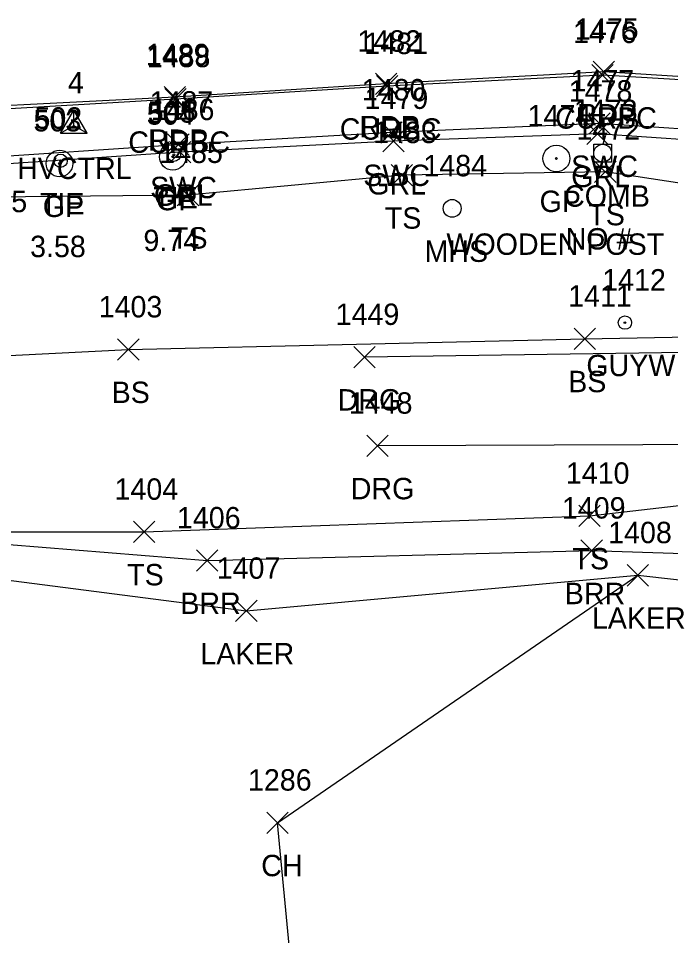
# Model space of a CAD drawing. Extents: x 1716490 to 1717645, y 888034 to 890004.
# Drawn here: x 1717454.4 to 1717515.4, y 888173.5 to 888259.2 of the extents above; entities that cross this region are included whole.
import ezdxf

# ---------------------------------------------------------------- set-up
doc = ezdxf.new("R2010")
doc.units = 0
for name, color, linetype in [('C_A', 7, 'Continuous'), ('C_C', 7, 'Continuous'), ('C_I', 7, 'Continuous'), ('CBP', 7, 'Continuous'), ('CPSM', 7, 'Continuous'), ('L_A', 7, 'Continuous'), ('L_I', 7, 'Continuous'), ('L_TIC', 7, 'Continuous'), ('LABL', 7, 'Continuous'), ('LAWE', 7, 'Continuous'), ('LELB', 7, 'Continuous'), ('LSOGP', 7, 'Continuous'), ('P_A', 7, 'Continuous'), ('P_I', 7, 'Continuous'), ('P_TIC', 7, 'Continuous'), ('PET', 7, 'Continuous'), ('R_A', 7, 'Continuous'), ('R_C', 7, 'Continuous'), ('R_I', 7, 'Continuous'), ('R_TIC', 7, 'Continuous'), ('RC', 7, 'Continuous'), ('RDG', 7, 'Continuous'), ('RGP', 7, 'Continuous'), ('RGR', 7, 'Continuous'), ('RSW', 7, 'Continuous'), ('U_A', 7, 'Continuous'), ('U_C', 7, 'Continuous'), ('U_I', 7, 'Continuous'), ('UP', 7, 'Continuous'), ('UPGW', 7, 'Continuous'), ('USMH', 7, 'Continuous')]:
    doc.layers.add(name, color=color, linetype=linetype)

msp = doc.modelspace()

# ---------------------------------------------------------------- linework, layer by layer
at = {"layer": 'CBP'}
for centre, radius in [((1717468.983, 888246.436), 0.625), ((1717458.391, 888245.871), 0.625), ((1717468.983, 888246.436), 0.0833), ((1717458.391, 888245.871), 0.0833)]:
    msp.add_circle(centre, radius, dxfattribs=at)
at = {"layer": 'CPSM'}
for p, q in [((1717458.388, 888248.452), (1717459.638, 888250.617)), ((1717458.388, 888248.452), (1717459.638, 888250.617)), ((1717458.388, 888248.452), (1717459.638, 888250.617)), ((1717458.388, 888248.452), (1717459.638, 888250.617)), ((1717458.388, 888248.452), (1717459.638, 888250.617)), ((1717458.388, 888248.452), (1717459.638, 888250.617)), ((1717458.388, 888248.452), (1717459.638, 888250.617)), ((1717458.388, 888248.452), (1717459.638, 888250.617)), ((1717458.388, 888248.452), (1717459.638, 888250.617)), ((1717460.888, 888248.452), (1717459.638, 888250.617)), ((1717459.638, 888249.173), (1717459.638, 888250.617)), ((1717460.888, 888248.452), (1717459.638, 888250.617)), ((1717459.638, 888249.173), (1717459.638, 888250.617)), ((1717460.888, 888248.452), (1717459.638, 888250.617)), ((1717459.638, 888249.173), (1717459.638, 888250.617)), ((1717460.888, 888248.452), (1717459.638, 888250.617)), ((1717459.638, 888249.173), (1717459.638, 888250.617)), ((1717460.888, 888248.452), (1717459.638, 888250.617)), ((1717459.638, 888249.173), (1717459.638, 888250.617)), ((1717460.888, 888248.452), (1717459.638, 888250.617)), ((1717459.638, 888249.173), (1717459.638, 888250.617)), ((1717460.888, 888248.452), (1717459.638, 888250.617)), ((1717459.638, 888249.173), (1717459.638, 888250.617)), ((1717460.888, 888248.452), (1717459.638, 888250.617)), ((1717459.638, 888249.173), (1717459.638, 888250.617)), ((1717460.888, 888248.452), (1717459.638, 888250.617)), ((1717459.638, 888249.173), (1717459.638, 888250.617)), ((1717458.388, 888248.452), (1717459.638, 888249.173)), ((1717458.388, 888248.452), (1717459.638, 888249.173)), ((1717458.388, 888248.452), (1717459.638, 888249.173)), ((1717458.388, 888248.452), (1717459.638, 888249.173)), ((1717458.388, 888248.452), (1717459.638, 888249.173)), ((1717458.388, 888248.452), (1717459.638, 888249.173)), ((1717458.388, 888248.452), (1717459.638, 888249.173)), ((1717458.388, 888248.452), (1717459.638, 888249.173)), ((1717458.388, 888248.452), (1717459.638, 888249.173)), ((1717459.638, 888249.173), (1717459.638, 888249.173)), ((1717459.638, 888249.173), (1717460.888, 888248.452)), ((1717459.638, 888249.173), (1717459.638, 888249.173)), ((1717459.638, 888249.173), (1717460.888, 888248.452)), ((1717459.638, 888249.173), (1717459.638, 888249.173)), ((1717459.638, 888249.173), (1717460.888, 888248.452)), ((1717459.638, 888249.173), (1717459.638, 888249.173)), ((1717459.638, 888249.173), (1717460.888, 888248.452)), ((1717459.638, 888249.173), (1717459.638, 888249.173)), ((1717459.638, 888249.173), (1717460.888, 888248.452)), ((1717459.638, 888249.173), (1717459.638, 888249.173)), ((1717459.638, 888249.173), (1717460.888, 888248.452)), ((1717459.638, 888249.173), (1717459.638, 888249.173)), ((1717459.638, 888249.173), (1717460.888, 888248.452)), ((1717459.638, 888249.173), (1717459.638, 888249.173)), ((1717459.638, 888249.173), (1717460.888, 888248.452)), ((1717459.638, 888249.173), (1717459.638, 888249.173)), ((1717459.638, 888249.173), (1717460.888, 888248.452)), ((1717458.388, 888248.452), (1717460.888, 888248.452)), ((1717458.388, 888248.452), (1717460.888, 888248.452)), ((1717458.388, 888248.452), (1717460.888, 888248.452)), ((1717458.388, 888248.452), (1717460.888, 888248.452)), ((1717458.388, 888248.452), (1717460.888, 888248.452)), ((1717458.388, 888248.452), (1717460.888, 888248.452)), ((1717458.388, 888248.452), (1717460.888, 888248.452)), ((1717458.388, 888248.452), (1717460.888, 888248.452)), ((1717458.388, 888248.452), (1717460.888, 888248.452))]:
    msp.add_line(p, q, dxfattribs=at)
at = {"layer": 'L_TIC'}
for points in [[(1717489.286, 888243.528), (1717491.286, 888245.528)], [(1717491.286, 888243.528), (1717489.286, 888245.528)], [(1717508.305, 888243.845), (1717510.305, 888245.845)], [(1717510.305, 888243.845), (1717508.305, 888245.845)], [(1717469.299, 888241.67), (1717471.299, 888243.67)], [(1717471.299, 888241.67), (1717469.299, 888243.67)], [(1717506.391, 888228.249), (1717508.391, 888230.249)], [(1717508.391, 888228.249), (1717506.391, 888230.249)], [(1717463.721, 888227.238), (1717465.721, 888229.238)], [(1717465.721, 888227.238), (1717463.721, 888229.238)], [(1717506.829, 888211.694), (1717508.829, 888213.694)], [(1717508.829, 888211.694), (1717506.829, 888213.694)], [(1717465.203, 888210.198), (1717467.203, 888212.198)], [(1717467.203, 888210.198), (1717465.203, 888212.198)], [(1717507.027, 888208.443), (1717509.027, 888210.443)], [(1717509.027, 888208.443), (1717507.027, 888210.443)], [(1717471.093, 888207.525), (1717473.093, 888209.525)], [(1717473.093, 888207.525), (1717471.093, 888209.525)], [(1717511.343, 888206.141), (1717513.343, 888208.141)], [(1717513.343, 888206.141), (1717511.343, 888208.141)], [(1717474.751, 888202.813), (1717476.751, 888204.813)], [(1717476.751, 888202.813), (1717474.751, 888204.813)], [(1717477.654, 888183.022), (1717479.654, 888185.022)], [(1717479.654, 888183.022), (1717477.654, 888185.022)]]:
    msp.add_lwpolyline(points, dxfattribs=at)
at = {"layer": 'LABL'}
msp.add_lwpolyline([(1717444.304, 888210.768), (1717472.093, 888208.525), (1717508.027, 888209.443), (1717543.383, 888208.313), (1717559.79, 888208.697), (1717569.184, 888204.287)], dxfattribs=at)
at = {"layer": 'LAWE'}
msp.add_lwpolyline([(1717435.889, 888208.946), (1717475.751, 888203.813), (1717512.343, 888207.141), (1717547.357, 888203.244), (1717562.879, 888195.852), (1717574.347, 888181.764)], dxfattribs=at)
at = {"layer": 'LELB'}
for points in [[(1717558.191, 888231.225), (1717550.825, 888235.094), (1717537.711, 888239.81), (1717528.963, 888241.86), (1717509.305, 888244.845), (1717490.286, 888244.528), (1717470.299, 888242.67), (1717436.838, 888242.33)], [(1717436.262, 888226.802), (1717464.721, 888228.238), (1717507.391, 888229.249), (1717536.749, 888229.804)], [(1717436.472, 888211.206), (1717466.203, 888211.198), (1717507.829, 888212.694), (1717537.791, 888216.149), (1717563.771, 888215.069), (1717574.805, 888210.491), (1717582.49, 888199.54), (1717589.339, 888189.724)]]:
    msp.add_lwpolyline(points, dxfattribs=at)
at = {"layer": 'LSOGP'}
msp.add_lwpolyline([(1717483.447, 888133.722), (1717478.655, 888184.022), (1717512.343, 888207.141), (1717547.357, 888203.244)], dxfattribs=at)
at = {"layer": 'P_TIC'}
for points in [[(1717508.155, 888253.185), (1717510.155, 888255.185)], [(1717510.155, 888253.185), (1717508.155, 888255.185)], [(1717487.825, 888252.07), (1717489.825, 888254.07)], [(1717489.825, 888252.07), (1717487.825, 888254.07)], [(1717468.068, 888250.805), (1717470.068, 888252.805)], [(1717470.068, 888250.805), (1717468.068, 888252.805)]]:
    msp.add_lwpolyline(points, dxfattribs=at)
at = {"layer": 'PET'}
msp.add_lwpolyline([(1717594.517, 888190.334), (1717590.366, 888197.636), (1717582.375, 888209.703), (1717579.255, 888214.07), (1717576.4, 888218.115), (1717565.946, 888231.02), (1717560.234, 888236.413), (1717554.367, 888241.047), (1717546.423, 888245.577), (1717533.805, 888250.762), (1717523.466, 888253.269), (1717509.155, 888254.185), (1717488.825, 888253.07), (1717469.068, 888251.805), (1717449.414, 888250.828), (1717439.895, 888250.333)], dxfattribs=at)
at = {"layer": 'R_TIC'}
for points in [[(1717508.034, 888252.878), (1717510.034, 888254.878)], [(1717510.034, 888252.878), (1717508.034, 888254.878)], [(1717487.904, 888251.846), (1717489.904, 888253.846)], [(1717489.904, 888251.846), (1717487.904, 888253.846)], [(1717468.137, 888250.622), (1717470.137, 888252.622)], [(1717470.137, 888250.622), (1717468.137, 888252.622)], [(1717507.753, 888248.365), (1717509.753, 888250.365)], [(1717509.753, 888248.365), (1717507.753, 888250.365)], [(1717488.316, 888247.516), (1717490.316, 888249.516)], [(1717490.316, 888247.516), (1717488.316, 888249.516)], [(1717488.509, 888246.722), (1717490.509, 888248.722)], [(1717490.509, 888246.722), (1717488.509, 888248.722)], [(1717507.577, 888247.408), (1717509.577, 888249.408)], [(1717509.577, 888247.408), (1717507.577, 888249.408)], [(1717468.398, 888246.378), (1717470.398, 888248.378)], [(1717470.398, 888246.378), (1717468.398, 888248.378)], [(1717468.569, 888245.675), (1717470.569, 888247.675)], [(1717470.569, 888245.675), (1717468.569, 888247.675)], [(1717485.801, 888226.536), (1717487.801, 888228.536)], [(1717487.801, 888226.536), (1717485.801, 888228.536)], [(1717487.023, 888218.244), (1717489.023, 888220.244)], [(1717489.023, 888218.244), (1717487.023, 888220.244)]]:
    msp.add_lwpolyline(points, dxfattribs=at)
at = {"layer": 'RC'}
msp.add_lwpolyline([(1717594.157, 888190.547), (1717590.511, 888197.229), (1717582.134, 888209.508), (1717579.157, 888213.908), (1717576.185, 888218.151), (1717565.853, 888230.61), (1717559.89, 888236.254), (1717554.327, 888240.707), (1717546.304, 888245.431), (1717533.609, 888250.562), (1717523.635, 888253.005), (1717509.034, 888253.878), (1717488.904, 888252.846), (1717469.137, 888251.622), (1717449.343, 888250.478), (1717439.503, 888250.043)], dxfattribs=at)
at = {"layer": 'RDG'}
for points in [[(1717562.584, 888227.864), (1717551.957, 888228.253), (1717529.512, 888228.139), (1717486.801, 888227.536)], [(1717569.563, 888218.728), (1717554.945, 888217.732), (1717529.31, 888219.394), (1717488.023, 888219.244)]]:
    msp.add_lwpolyline(points, dxfattribs=at)
at = {"layer": 'RGP'}
for p, q in [((1717468.876, 888246.251), (1717468.876, 888246.251)), ((1717504.729, 888246.086), (1717504.729, 888246.086)), ((1717458.291, 888245.62), (1717458.291, 888245.62))]:
    msp.add_line(p, q, dxfattribs=at)
for centre, radius in [((1717458.291, 888245.62), 1.25), ((1717468.876, 888246.251), 1.25), ((1717504.729, 888246.086), 1.25), ((1717468.876, 888246.251), 0.0833), ((1717504.729, 888246.086), 0.0833), ((1717458.291, 888245.62), 0.0833)]:
    msp.add_circle(centre, radius, dxfattribs=at)
at = {"layer": 'RGR'}
msp.add_lwpolyline([(1717550.825, 888235.094), (1717542.337, 888240.035), (1717527.82, 888245.616), (1717517.741, 888247.772), (1717508.577, 888248.408), (1717489.509, 888247.722), (1717469.569, 888246.675), (1717449.392, 888245.322), (1717432.288, 888244.31)], dxfattribs=at)
at = {"layer": 'RSW'}
msp.add_lwpolyline([(1717590.097, 888189.333), (1717586.586, 888194.982), (1717578.896, 888206.737), (1717575.658, 888211.348), (1717571.853, 888216.425), (1717562.584, 888227.864), (1717557.01, 888233.176), (1717551.758, 888236.948), (1717544.051, 888241.46), (1717532.127, 888246.38), (1717522.616, 888248.419), (1717508.753, 888249.365), (1717489.316, 888248.516), (1717469.398, 888247.378), (1717449.774, 888246.071), (1717439.35, 888245.712)], dxfattribs=at)
at = {"layer": 'UP'}
for p, q in [((1717509.311, 888248.249), (1717509.061, 888247.416)), ((1717508.227, 888245.749), (1717508.227, 888247.416)), ((1717508.227, 888247.416), (1717509.894, 888247.416)), ((1717509.894, 888247.416), (1717509.894, 888245.749)), ((1717509.061, 888246.582), (1717509.061, 888246.582)), ((1717509.894, 888245.749), (1717508.227, 888245.749)), ((1717508.811, 888244.916), (1717509.061, 888245.749))]:
    msp.add_line(p, q, dxfattribs=at)
msp.add_circle((1717509.061, 888246.582), 0.833, dxfattribs=at)
at = {"layer": 'UPGW'}
for radius in [0.625, 0.0833]:
    msp.add_circle((1717511.139, 888230.751), radius, dxfattribs=at)
at = {"layer": 'USMH'}
for p, q in [((1717494.992, 888241.426), (1717494.992, 888241.426)), ((1717495.826, 888241.426), (1717495.826, 888241.426))]:
    msp.add_line(p, q, dxfattribs=at)
msp.add_circle((1717494.992, 888241.426), 0.833, dxfattribs=at)

# ---------------------------------------------------------------- texts
at = {"layer": 'C_A'}
for s, p in [('HVCTRL', (1717454.331, 888244.173)), ('HVCTRL', (1717454.331, 888244.173)), ('HVCTRL', (1717454.331, 888244.173)), ('HVCTRL', (1717454.331, 888244.173)), ('HVCTRL', (1717454.331, 888244.173)), ('HVCTRL', (1717454.331, 888244.173)), ('HVCTRL', (1717454.331, 888244.173)), ('HVCTRL', (1717454.331, 888244.173)), ('HVCTRL', (1717454.331, 888244.173)), ('TIE', (1717467.062, 888241.436)), ('TIE', (1717456.469, 888240.871))]:
    msp.add_text(s, height=2, dxfattribs=at).set_placement(p)
at = {"layer": 'C_C'}
for s, p in [('9.74', (1717466.133, 888237.436)), ('3.58', (1717455.54, 888236.871))]:
    msp.add_text(s, height=2, dxfattribs=at).set_placement(p)
at = {"layer": 'C_I'}
for s, p in [('4', (1717459.071, 888252.173)), ('4', (1717459.071, 888252.173)), ('4', (1717459.071, 888252.173)), ('4', (1717459.071, 888252.173)), ('4', (1717459.071, 888252.173)), ('4', (1717459.071, 888252.173)), ('4', (1717459.071, 888252.173)), ('4', (1717459.071, 888252.173)), ('4', (1717459.071, 888252.173)), ('505', (1717466.542, 888249.436)), ('502', (1717455.95, 888248.871))]:
    msp.add_text(s, height=2, dxfattribs=at).set_placement(p)
at = {"layer": 'L_A'}
for s, p in [('TS', (1717507.715, 888239.845)), ('TS', (1717488.695, 888239.528)), ('TS', (1717468.709, 888237.67)), ('BS', (1717505.832, 888224.249)), ('BS', (1717463.162, 888223.238)), ('TS', (1717506.238, 888207.694)), ('TS', (1717464.613, 888206.198)), ('BRR', (1717505.515, 888204.443)), ('BRR', (1717469.581, 888203.525)), ('LAKER', (1717508.052, 888202.141)), ('LAKER', (1717471.459, 888198.813)), ('CH', (1717477.143, 888179.022))]:
    msp.add_text(s, height=2, dxfattribs=at).set_placement(p)
at = {"layer": 'L_I'}
for s, p in [('1483', (1717487.593, 888247.528)), ('1472', (1717506.612, 888247.845)), ('1485', (1717467.607, 888245.67)), ('1411', (1717505.832, 888232.249)), ('1403', (1717461.95, 888231.238)), ('1410', (1717505.616, 888215.694)), ('1404', (1717463.432, 888214.198)), ('1409', (1717505.247, 888212.443)), ('1406', (1717469.266, 888211.525)), ('1408', (1717509.572, 888210.141)), ('1407', (1717472.979, 888206.813)), ('1286', (1717475.906, 888187.022))]:
    msp.add_text(s, height=2, dxfattribs=at).set_placement(p)
at = {"layer": 'P_A'}
for p in [(1717506.643, 888249.185), (1717486.313, 888248.07), (1717466.557, 888246.805)]:
    msp.add_text('RDP', height=2, dxfattribs=at).set_placement(p)
at = {"layer": 'P_I'}
for s, p in [('1475', (1717506.462, 888257.185)), ('1482', (1717486.132, 888256.07)), ('1489', (1717466.368, 888254.805))]:
    msp.add_text(s, height=2, dxfattribs=at).set_placement(p)
at = {"layer": 'R_A'}
for s, p in [('CURBC', (1717504.617, 888248.878)), ('CURBC', (1717484.486, 888247.846)), ('CURBC', (1717464.72, 888246.622)), ('SWC', (1717506.115, 888244.365)), ('SWC', (1717486.678, 888243.516)), ('GRL', (1717506.12, 888243.408)), ('SWC', (1717466.76, 888242.378)), ('GRL', (1717487.052, 888242.722)), ('GRL', (1717467.112, 888241.675)), ('SWC TS5', (1717443.38, 888241.071)), ('GP', (1717456.724, 888240.62)), ('GP', (1717467.309, 888241.251)), ('GP', (1717503.162, 888241.086)), ('DRG', (1717484.289, 888222.536)), ('DRG', (1717485.512, 888214.244))]:
    msp.add_text(s, height=2, dxfattribs=at).set_placement(p)
at = {"layer": 'R_C'}
msp.add_text('WOODEN POST', height=2, dxfattribs=at).set_placement((1717494.454, 888237.086))
at = {"layer": 'R_I'}
for s, p in [('1476', (1717506.286, 888256.878)), ('1481', (1717486.778, 888255.846)), ('1488', (1717466.444, 888254.622)), ('1477', (1717506.06, 888252.365)), ('1480', (1717486.537, 888251.516)), ('1478', (1717505.884, 888251.408)), ('1487', (1717466.705, 888250.378)), ('1479', (1717486.808, 888250.722)), ('504', (1717466.435, 888249.251)), ('1486', (1717466.821, 888249.675)), ('503', (1717455.85, 888248.62)), ('1474', (1717502.036, 888249.086)), ('1449', (1717484.1, 888230.536)), ('1448', (1717485.331, 888222.244))]:
    msp.add_text(s, height=2, dxfattribs=at).set_placement(p)
at = {"layer": 'U_A'}
for s, p in [('COMB', (1717505.447, 888241.582)), ('MHS', (1717492.41, 888236.426)), ('GUYW', (1717507.533, 888225.751))]:
    msp.add_text(s, height=2, dxfattribs=at).set_placement(p)
at = {"layer": 'U_C'}
msp.add_text('NO #', height=2, dxfattribs=at).set_placement((1717505.596, 888237.582))
at = {"layer": 'U_I'}
for s, p in [('1473', (1717506.368, 888249.582)), ('1484', (1717492.299, 888244.426)), ('1412', (1717509.013, 888233.751))]:
    msp.add_text(s, height=2, dxfattribs=at).set_placement(p)

doc.saveas('drawing.dxf')
